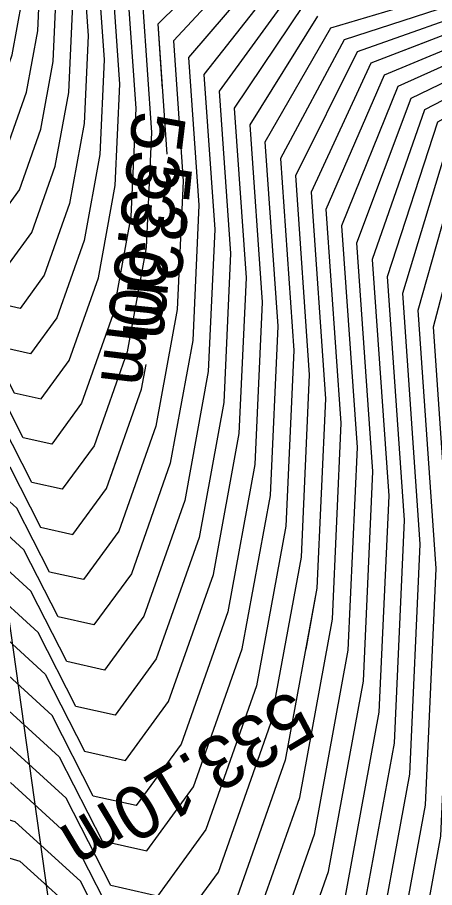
# Model space of a CAD drawing. Extents: x -866683 to -866410, y -1041951 to -1040252.
# Drawn here: x -866454.853 to -866452.485, y -1041929.09 to -1041924.155 of the extents above; entities that cross this region are included whole.
import ezdxf

# ---------------------------------------------------------------- set-up
doc = ezdxf.new("R2010")
doc.units = 0
for name, color, linetype in [('BREAKLINE', 7, 'Continuous'), ('V-HL', 7, 'Continuous'), ('V-POPIS', 7, 'Continuous'), ('V-VEDL', 7, 'Continuous'), ('V_po_cm', 7, 'Continuous')]:
    doc.layers.add(name, color=color, linetype=linetype)

msp = doc.modelspace()

# ---------------------------------------------------------------- linework, layer by layer
at = {"layer": 'BREAKLINE'}
msp.add_lwpolyline([(-866451.679, -1041950.508), (-866455.618, -1041922.473), (-866456.719, -1041912.396), (-866455.207, -1041909.853), (-866453.752, -1041908.342), (-866450, -1041907.538), (-866447.7, -1041908.076), (-866445.165, -1041909.459), (-866437.422, -1041915.176), (-866426.565, -1041925.108), (-866438.22, -1041915.868), (-866445.312, -1041910.554), (-866447.7, -1041908.076)], dxfattribs=at)
at = {"layer": 'V-HL'}
for points in [[(-866454.0036, -1041924.9299), (-866454.0551, -1041924.1916), (-866453.6066, -1041923.7495), (-866452.6571, -1041923.6189), (-866449.7561, -1041923.981)], [(-866456.1597, -1041926.4733), (-866455.4344, -1041926.3983), (-866455.1343, -1041926.4876), (-866454.8967, -1041926.7037), (-866454.7217, -1041927.0466), (-866454.5387, -1041927.0874), (-866454.3478, -1041926.8261), (-866454.1489, -1041926.2626), (-866454.1234, -1041926.1239)]]:
    msp.add_lwpolyline(points, dxfattribs=at)
at = {"layer": 'V-VEDL'}
msp.add_lwpolyline([(-866449.7169, -1041924.4172), (-866452.0847, -1041924.1217), (-866452.8467, -1041924.414), (-866453.1868, -1041925.1464), (-866453.1051, -1041926.3188), (-866453.1537, -1041927.3927), (-866453.3327, -1041928.3679), (-866453.6421, -1041929.2445), (-866453.9391, -1041929.651), (-866454.2237, -1041929.5876), (-866454.496, -1041929.0541), (-866454.8656, -1041928.7179), (-866455.3324, -1041928.579), (-866456.4607, -1041928.6957)], dxfattribs=at)
at = {"layer": 'V_po_cm'}
for points in [[(-866462.1027, -1041925.5108), (-866461.798, -1041925.2446), (-866461.0568, -1041925.085), (-866459.7267, -1041924.8987), (-866457.8078, -1041924.6859), (-866456.4681, -1041924.5378), (-866455.7075, -1041924.4544), (-866455.5262, -1041924.4356), (-866455.3761, -1041924.4803), (-866455.2574, -1041924.5883), (-866455.1698, -1041924.7598), (-866455.0783, -1041924.7802), (-866454.9829, -1041924.6495), (-866454.8834, -1041924.3678), (-866454.8259, -1041924.0543), (-866454.8103, -1041923.7092), (-866454.8365, -1041923.3323), (-866454.2906, -1041923.1514), (-866453.1723, -1041923.1664), (-866451.4819, -1041923.3774), (-866450.2106, -1041923.4801), (-866449.3586, -1041923.4745), (-866448.9258, -1041923.3605)], [(-866462.0827, -1041925.7352), (-866461.7712, -1041925.4631), (-866461.0344, -1041925.3022), (-866459.7166, -1041925.1165), (-866457.8178, -1041924.906), (-866456.4847, -1041924.7586), (-866455.7175, -1041924.6745), (-866455.516, -1041924.6537), (-866455.3493, -1041924.7033), (-866455.2173, -1041924.8234), (-866455.12, -1041925.0139), (-866455.0184, -1041925.0366), (-866454.9123, -1041924.8914), (-866454.8018, -1041924.5783), (-866454.7379, -1041924.23), (-866454.7205, -1041923.8465), (-866454.7497, -1041923.4278), (-866454.2146, -1041923.2178), (-866453.1151, -1041923.2167), (-866451.4513, -1041923.4244), (-866450.2001, -1041923.5254), (-866449.3615, -1041923.5199), (-866448.9355, -1041923.4077)], [(-866462.0626, -1041925.9596), (-866461.7444, -1041925.6816), (-866461.0121, -1041925.5195), (-866459.7065, -1041925.3343), (-866457.8278, -1041925.126), (-866456.5014, -1041924.9794), (-866455.7274, -1041924.8947), (-866455.5058, -1041924.8718), (-866455.3224, -1041924.9263), (-866455.1772, -1041925.0584), (-866455.0702, -1041925.268), (-866454.9584, -1041925.2929), (-866454.8417, -1041925.1332), (-866454.7202, -1041924.7888), (-866454.6499, -1041924.4057), (-866454.6308, -1041923.9839), (-866454.6629, -1041923.5233), (-866454.1386, -1041923.2843), (-866453.0579, -1041923.267), (-866451.4207, -1041923.4713), (-866450.1896, -1041923.5708), (-866449.3644, -1041923.5653), (-866448.9453, -1041923.4549)], [(-866462.0426, -1041926.184), (-866461.7176, -1041925.9001), (-866460.9897, -1041925.7368), (-866459.6965, -1041925.5521), (-866457.8378, -1041925.346), (-866456.5181, -1041925.2002), (-866455.7374, -1041925.1149), (-866455.4956, -1041925.0898), (-866455.2955, -1041925.1494), (-866455.1371, -1041925.2935), (-866455.0204, -1041925.5221), (-866454.8985, -1041925.5493), (-866454.7712, -1041925.3751), (-866454.6386, -1041924.9994), (-866454.5619, -1041924.5814), (-866454.541, -1041924.1212), (-866454.5761, -1041923.6187), (-866454.0626, -1041923.3508), (-866453.0006, -1041923.3173), (-866451.3901, -1041923.5183), (-866450.179, -1041923.6161), (-866449.3673, -1041923.6107), (-866448.955, -1041923.5022)], [(-866448.9647, -1041923.5494), (-866449.3702, -1041923.6561), (-866450.1685, -1041923.6614), (-866451.3595, -1041923.5652), (-866452.9434, -1041923.3675), (-866453.9866, -1041923.4172), (-866454.4892, -1041923.7142), (-866454.4513, -1041924.2586), (-866454.4739, -1041924.7571), (-866454.557, -1041925.2099), (-866454.7006, -1041925.6169), (-866454.8385, -1041925.8056), (-866454.9707, -1041925.7762), (-866455.0971, -1041925.5285), (-866455.2687, -1041925.3724), (-866455.4854, -1041925.3079), (-866455.7473, -1041925.335), (-866456.5348, -1041925.421), (-866457.8478, -1041925.566), (-866459.6864, -1041925.7699), (-866460.9674, -1041925.9541), (-866461.6908, -1041926.1186), (-866462.0225, -1041926.4084)], [(-866448.9745, -1041923.5966), (-866449.3731, -1041923.7016), (-866450.158, -1041923.7067), (-866451.329, -1041923.6122), (-866452.8861, -1041923.4178), (-866453.9106, -1041923.4837), (-866454.4024, -1041923.8097), (-866454.3615, -1041924.3959), (-866454.3859, -1041924.9328), (-866454.4753, -1041925.4204), (-866454.63, -1041925.8587), (-866454.7785, -1041926.062), (-866454.9209, -1041926.0303), (-866455.057, -1041925.7635), (-866455.2418, -1041925.5954), (-866455.4752, -1041925.526), (-866455.7573, -1041925.5552), (-866456.5515, -1041925.6418), (-866457.8578, -1041925.786), (-866459.6763, -1041925.9876), (-866460.945, -1041926.1714), (-866461.664, -1041926.3371), (-866462.0025, -1041926.6328)], [(-866461.9824, -1041926.8572), (-866461.6372, -1041926.5556), (-866460.9226, -1041926.3886), (-866459.6662, -1041926.2054), (-866457.8678, -1041926.006), (-866456.5682, -1041925.8626), (-866455.7672, -1041925.7753), (-866455.465, -1041925.7441), (-866455.2149, -1041925.8185), (-866455.0169, -1041925.9986), (-866454.8711, -1041926.2844), (-866454.7186, -1041926.3184), (-866454.5595, -1041926.1006), (-866454.3937, -1041925.631), (-866454.2978, -1041925.1085), (-866454.2718, -1041924.5333), (-866454.3156, -1041923.9052), (-866453.8346, -1041923.5501), (-866452.8289, -1041923.4681), (-866451.2984, -1041923.6591), (-866450.1474, -1041923.7521), (-866449.376, -1041923.747), (-866448.9842, -1041923.6438)], [(-866448.9939, -1041923.691), (-866449.379, -1041923.7924), (-866450.1369, -1041923.7974), (-866451.2678, -1041923.7061), (-866452.7716, -1041923.5184), (-866453.7586, -1041923.6166), (-866454.2288, -1041924.0007), (-866454.182, -1041924.6706), (-866454.2098, -1041925.2842), (-866454.3121, -1041925.8415), (-866454.4889, -1041926.3424), (-866454.6586, -1041926.5747), (-866454.8213, -1041926.5385), (-866454.9769, -1041926.2336), (-866455.188, -1041926.0415), (-866455.4548, -1041925.9621), (-866455.7772, -1041925.9955), (-866456.5848, -1041926.0834), (-866457.8778, -1041926.226), (-866459.6561, -1041926.4232), (-866460.9003, -1041926.6059), (-866461.6104, -1041926.7741), (-866461.9624, -1041927.0816)], [(-866449.0037, -1041923.7382), (-866449.3819, -1041923.8378), (-866450.1264, -1041923.8427), (-866451.2372, -1041923.753), (-866452.7144, -1041923.5686), (-866453.6826, -1041923.683), (-866454.1419, -1041924.0961), (-866454.0923, -1041924.808), (-866454.1218, -1041925.4599), (-866454.2305, -1041926.052), (-866454.4183, -1041926.5842), (-866454.5986, -1041926.8311), (-866454.7715, -1041926.7926), (-866454.9368, -1041926.4687), (-866455.1612, -1041926.2645), (-866455.4446, -1041926.1802), (-866455.7871, -1041926.2156), (-866456.6015, -1041926.3042), (-866457.8878, -1041926.446), (-866459.646, -1041926.641), (-866460.8779, -1041926.8232), (-866461.5836, -1041926.9926), (-866461.9423, -1041927.306)], [(-866454.0294, -1041924.5605), (-866454.0551, -1041924.1916), (-866453.6066, -1041923.7495), (-866452.6571, -1041923.6189), (-866451.2066, -1041923.8), (-866450.4417, -1041923.8617)], [(-866449.0232, -1041923.8327), (-866449.3877, -1041923.9286), (-866450.1053, -1041923.9334), (-866451.176, -1041923.8469), (-866452.5999, -1041923.6692), (-866453.5306, -1041923.8159), (-866453.9683, -1041924.2871), (-866453.9128, -1041925.0827), (-866453.9458, -1041925.8113), (-866454.0673, -1041926.4731), (-866454.2772, -1041927.0679), (-866454.4787, -1041927.3438), (-866454.6719, -1041927.3007), (-866454.8566, -1041926.9387), (-866455.1074, -1041926.7106), (-866455.4242, -1041926.6163), (-866455.807, -1041926.6559), (-866456.6349, -1041926.7458), (-866457.9078, -1041926.8861), (-866459.6258, -1041927.0766), (-866460.8332, -1041927.2578), (-866461.53, -1041927.4297), (-866461.9022, -1041927.7548)], [(-866449.0329, -1041923.8799), (-866449.3906, -1041923.9741), (-866450.0948, -1041923.9787), (-866451.1455, -1041923.8939), (-866452.5426, -1041923.7195), (-866453.4546, -1041923.8824), (-866453.8814, -1041924.3826), (-866453.8231, -1041925.22), (-866453.8578, -1041925.987), (-866453.9856, -1041926.6836), (-866454.2066, -1041927.3098), (-866454.4188, -1041927.6002), (-866454.6221, -1041927.5548), (-866454.8166, -1041927.1738), (-866455.0806, -1041926.9336), (-866455.414, -1041926.8344), (-866455.817, -1041926.8761), (-866456.6516, -1041926.9666), (-866457.9178, -1041927.1061), (-866459.6157, -1041927.2943), (-866460.8108, -1041927.475), (-866461.5031, -1041927.6482), (-866461.8822, -1041927.9793)], [(-866449.0426, -1041923.9271), (-866449.3935, -1041924.0195), (-866450.0843, -1041924.0241), (-866451.1149, -1041923.9408), (-866452.4854, -1041923.7698), (-866453.3786, -1041923.9488), (-866453.7946, -1041924.478), (-866453.7333, -1041925.3574), (-866453.7698, -1041926.1628), (-866453.904, -1041926.8942), (-866454.136, -1041927.5516), (-866454.3588, -1041927.8565), (-866454.5723, -1041927.8089), (-866454.7765, -1041927.4088), (-866455.0537, -1041927.1567), (-866455.4038, -1041927.0525), (-866455.8269, -1041927.0963), (-866456.6682, -1041927.1875), (-866457.9278, -1041927.3261), (-866459.6056, -1041927.5121), (-866460.7885, -1041927.6923), (-866461.4763, -1041927.8667), (-866461.8621, -1041928.2037)], [(-866449.0524, -1041923.9743), (-866449.3964, -1041924.0649), (-866450.0737, -1041924.0694), (-866451.0843, -1041923.9878), (-866452.4282, -1041923.82), (-866453.3026, -1041924.0153), (-866453.7078, -1041924.5735), (-866453.6436, -1041925.4947), (-866453.6818, -1041926.3385), (-866453.8224, -1041927.1047), (-866454.0655, -1041927.7934), (-866454.2988, -1041928.1129), (-866454.5225, -1041928.063), (-866454.7364, -1041927.6439), (-866455.0268, -1041927.3797), (-866455.3936, -1041927.2706), (-866455.8369, -1041927.3164), (-866456.6849, -1041927.4083), (-866457.9378, -1041927.5461), (-866459.5955, -1041927.7299), (-866460.7661, -1041927.9096), (-866461.4495, -1041928.0852), (-866461.8421, -1041928.4281)], [(-866461.822, -1041928.6525), (-866461.4227, -1041928.3037), (-866460.7437, -1041928.1269), (-866459.5854, -1041927.9477), (-866457.9478, -1041927.7661), (-866456.7016, -1041927.6291), (-866455.8468, -1041927.5366), (-866455.3834, -1041927.4886), (-866454.9999, -1041927.6027), (-866454.6964, -1041927.8789), (-866454.4727, -1041928.3171), (-866454.2389, -1041928.3692), (-866453.9949, -1041928.0353), (-866453.7408, -1041927.3152), (-866453.5938, -1041926.5142), (-866453.5538, -1041925.6321), (-866453.621, -1041924.669), (-866453.2267, -1041924.0817), (-866452.3709, -1041923.8703), (-866451.0537, -1041924.0347), (-866450.0632, -1041924.1147), (-866449.3993, -1041924.1103), (-866449.0621, -1041924.0215)], [(-866461.7885, -1041929.0808), (-866461.77, -1041929.0821), (-866461.6974, -1041929.0245), (-866461.5614, -1041928.9087), (-866461.3621, -1041928.7345), (-866460.6967, -1041928.5594), (-866459.5653, -1041928.3833), (-866457.9678, -1041928.2061), (-866456.735, -1041928.0707), (-866455.8667, -1041927.9769), (-866455.363, -1041927.9248), (-866454.9462, -1041928.0488), (-866454.6162, -1041928.349), (-866454.3731, -1041928.8253), (-866454.119, -1041928.8819), (-866453.8538, -1041928.5189), (-866453.5776, -1041927.7363), (-866453.4177, -1041926.8656), (-866453.3743, -1041925.9068), (-866453.4473, -1041924.86), (-866453.0747, -1041924.2146), (-866452.2564, -1041923.9709)], [(-866449.0913, -1041924.1632), (-866449.408, -1041924.2466), (-866450.0316, -1041924.2507), (-866450.962, -1041924.1756), (-866452.1992, -1041924.0211), (-866452.9987, -1041924.2811), (-866453.3605, -1041924.9554), (-866453.2846, -1041926.0441), (-866453.3297, -1041927.0413), (-866453.4959, -1041927.9468), (-866453.7832, -1041928.7608), (-866454.059, -1041929.1383), (-866454.3233, -1041929.0794), (-866454.5761, -1041928.584), (-866454.9193, -1041928.2718)], [(-866454.8924, -1041928.4949), (-866454.5361, -1041928.819), (-866454.2735, -1041929.3335), (-866453.999, -1041929.3947), (-866453.7126, -1041929.0026), (-866453.4143, -1041928.1573), (-866453.2417, -1041927.217), (-866453.1948, -1041926.1815), (-866453.2736, -1041925.0509), (-866452.9227, -1041924.3476), (-866452.1419, -1041924.0714), (-866450.9314, -1041924.2225), (-866450.0211, -1041924.296), (-866449.4109, -1041924.292), (-866449.101, -1041924.2104)], [(-866453.1507, -1041924.1482), (-866453.5341, -1041924.7645), (-866453.4641, -1041925.7694), (-866453.5057, -1041926.6899), (-866453.6592, -1041927.5257), (-866453.9243, -1041928.2771), (-866454.1789, -1041928.6256), (-866454.4229, -1041928.5712), (-866454.6563, -1041928.1139), (-866454.9731, -1041927.8258), (-866455.3732, -1041927.7067), (-866455.8568, -1041927.7567), (-866456.7183, -1041927.8499), (-866457.9578, -1041927.9861), (-866459.5754, -1041928.1655), (-866460.721, -1041928.3438), (-866461.3947, -1041928.5212), (-866461.5966, -1041928.6975), (-866461.7317, -1041928.815), (-866461.8, -1041928.8737), (-866461.8031, -1041928.8735)], [(-866455.3222, -1041928.797), (-866454.8387, -1041928.9409), (-866454.4559, -1041929.2891), (-866454.1739, -1041929.8416), (-866453.8791, -1041929.9074), (-866453.5715, -1041929.4863), (-866453.2511, -1041928.5784), (-866453.0657, -1041927.5684), (-866453.0153, -1041926.4562), (-866453.1, -1041925.2419), (-866452.7707, -1041924.4805), (-866452.0274, -1041924.172), (-866450.8702, -1041924.3164), (-866450, -1041924.3867), (-866449.4168, -1041924.3828), (-866449.1205, -1041924.3048), (-866448.5277, -1041924.512)], [(-866448.5511, -1041924.5544), (-866449.1302, -1041924.352), (-866449.4197, -1041924.4282), (-866449.9895, -1041924.432), (-866450.8397, -1041924.3634), (-866451.9702, -1041924.2223), (-866452.6947, -1041924.5469), (-866453.0132, -1041925.3373), (-866452.9256, -1041926.5935), (-866452.9777, -1041927.7441), (-866453.1695, -1041928.7889), (-866453.5009, -1041929.7281), (-866453.8191, -1041930.1637), (-866454.1241, -1041930.0957), (-866454.4159, -1041929.5242), (-866454.8118, -1041929.164), (-866455.312, -1041929.0151)], [(-866455.3018, -1041929.2332), (-866454.785, -1041929.387), (-866454.3758, -1041929.7592), (-866454.0743, -1041930.3498), (-866453.7592, -1041930.4201), (-866453.4304, -1041929.97), (-866453.0878, -1041928.9995), (-866452.8897, -1041927.9198), (-866452.8358, -1041926.7309), (-866452.9263, -1041925.4328), (-866452.6187, -1041924.6134), (-866451.9129, -1041924.2725), (-866450.8091, -1041924.4103), (-866449.9789, -1041924.4773), (-866449.4226, -1041924.4737), (-866449.14, -1041924.3993), (-866448.5745, -1041924.5969)], [(-866452.5134, -1041924.2862), (-866452.8467, -1041924.414), (-866453.1868, -1041925.1464), (-866453.1051, -1041926.3188), (-866453.1537, -1041927.3927), (-866453.2172, -1041927.7386)], [(-866448.5979, -1041924.6393), (-866449.1497, -1041924.4465), (-866449.4255, -1041924.5191), (-866449.9684, -1041924.5227), (-866450.7785, -1041924.4573), (-866451.8557, -1041924.3228), (-866452.5427, -1041924.6798), (-866452.8395, -1041925.5283), (-866452.7461, -1041926.8682), (-866452.8017, -1041928.0955), (-866453.0062, -1041929.21), (-866453.3598, -1041930.2118), (-866453.6992, -1041930.6764), (-866454.0245, -1041930.6039), (-866454.3357, -1041929.9942), (-866454.7581, -1041929.61), (-866455.2916, -1041929.4513)], [(-866455.2814, -1041929.6693), (-866454.7312, -1041929.833), (-866454.2956, -1041930.2293), (-866453.9747, -1041930.858), (-866453.6393, -1041930.9328), (-866453.2892, -1041930.4536), (-866452.9246, -1041929.4205), (-866452.7136, -1041928.2712), (-866452.6563, -1041927.0056), (-866452.7527, -1041925.6238), (-866452.4667, -1041924.7463), (-866451.7985, -1041924.3731), (-866450.7479, -1041924.5042), (-866449.9579, -1041924.568), (-866449.4284, -1041924.5645), (-866449.1594, -1041924.4937), (-866448.6213, -1041924.6818)], [(-866455.2712, -1041929.8874), (-866454.7043, -1041930.0561), (-866454.2556, -1041930.4643), (-866453.9249, -1041931.1121), (-866453.5793, -1041931.1892), (-866453.2186, -1041930.6955), (-866452.843, -1041929.6311), (-866452.6256, -1041928.4469), (-866452.5666, -1041927.143), (-866452.6658, -1041925.7193), (-866452.3907, -1041924.8127), (-866451.7412, -1041924.4234), (-866450.7173, -1041924.5511), (-866449.9474, -1041924.6133), (-866449.4313, -1041924.6099), (-866449.1692, -1041924.5409), (-866448.6447, -1041924.7242)], [(-866455.261, -1041930.1055), (-866454.6775, -1041930.2791), (-866454.2155, -1041930.6994), (-866453.8751, -1041931.3662), (-866453.5193, -1041931.4455), (-866453.1481, -1041930.9373), (-866452.7614, -1041929.8416), (-866452.5376, -1041928.6226), (-866452.4768, -1041927.2803), (-866452.579, -1041925.8147), (-866452.3147, -1041924.8792), (-866451.684, -1041924.4736), (-866450.6867, -1041924.5981), (-866449.9368, -1041924.6587), (-866449.4342, -1041924.6553), (-866449.1789, -1041924.5881), (-866448.6681, -1041924.7666)], [(-866455.2508, -1041930.3235), (-866454.6506, -1041930.5021), (-866454.1754, -1041930.9344), (-866453.8253, -1041931.6203), (-866453.4594, -1041931.7019), (-866453.0775, -1041931.1792), (-866452.6798, -1041930.0521), (-866452.4496, -1041928.7983), (-866452.3871, -1041927.4177), (-866452.4922, -1041925.9102), (-866452.2387, -1041924.9456), (-866451.6267, -1041924.5239), (-866450.6562, -1041924.645), (-866449.9263, -1041924.704), (-866449.4371, -1041924.7008), (-866449.1886, -1041924.6353), (-866448.6915, -1041924.8091)], [(-866457.8867, -1041926.6648), (-866456.6182, -1041926.525), (-866455.7971, -1041926.4358), (-866455.4344, -1041926.3983), (-866455.1343, -1041926.4876), (-866454.8967, -1041926.7037), (-866454.7217, -1041927.0466), (-866454.5387, -1041927.0874), (-866454.3478, -1041926.8261), (-866454.2839, -1041926.645)], [(-866453.3954, -1041928.5454), (-866453.6421, -1041929.2445), (-866453.9391, -1041929.651), (-866454.2237, -1041929.5876), (-866454.4365, -1041929.1706)]]:
    msp.add_lwpolyline(points, dxfattribs=at)

# ---------------------------------------------------------------- texts
at = {"layer": 'V-POPIS'}
msp.add_text('533m', height=0.3, rotation=264.2659, dxfattribs=at).set_placement((-866454.158, -1041924.9676))
at = {"layer": 'V_po_cm'}
for s, rotation, p in [('533.00m', 263.0454, (-866454.1931, -1041924.6765)), ('533.10m', 210.982, (-866453.2946, -1041927.9601))]:
    msp.add_text(s, height=0.3, rotation=rotation, dxfattribs=at).set_placement(p)

doc.saveas('drawing.dxf')
